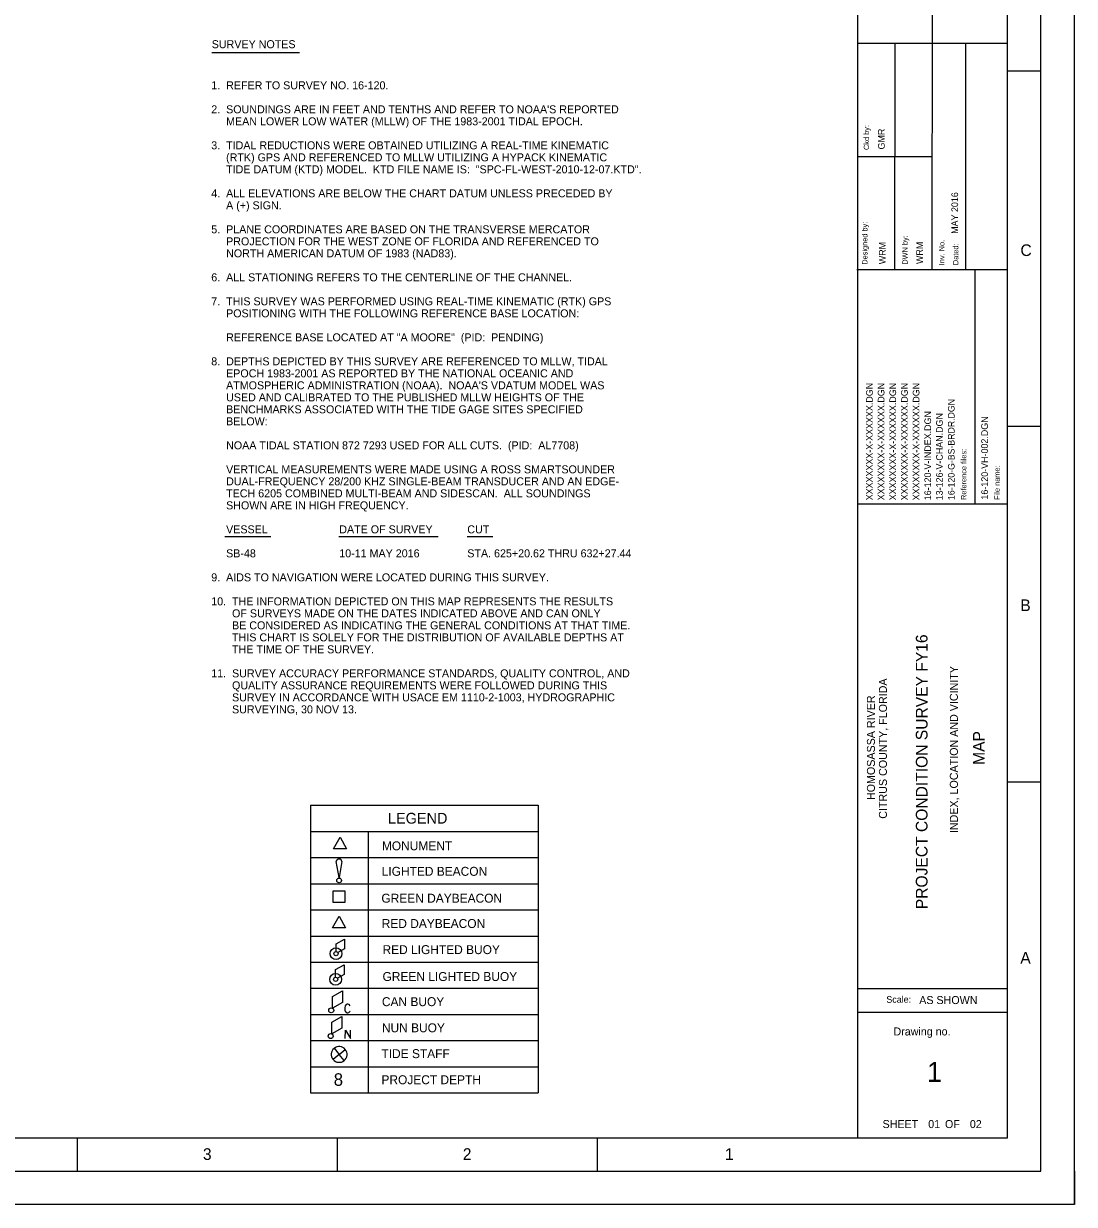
# Model space of a CAD drawing. Extents: x 384865 to 516869, y 1553900 to 1655899.
# Drawn here: x 469592 to 516869, y 1553900 to 1607032 of the extents above; entities that cross this region are included whole.
import ezdxf

# ---------------------------------------------------------------- set-up
doc = ezdxf.new("R2010")
doc.units = 0
for name, color, linetype in [('G-ANNO-NPLT', 7, 'Continuous'), ('G-ANNO-TEXT-DRWG', 7, 'Continuous'), ('G-ANNO-TEXT-PROJ', 7, 'Continuous'), ('G-ANNO-TEXT-TTLB', 7, 'Continuous'), ('G-ANNO-TTLB', 7, 'Continuous'), ('V-ANNO-LEGN', 7, 'Continuous'), ('V-ANNO-TEXT', 7, 'Continuous')]:
    doc.layers.add(name, color=color, linetype=linetype)

msp = doc.modelspace()

# ---------------------------------------------------------------- linework, layer by layer
at = {"layer": 'G-ANNO-NPLT'}
msp.add_lwpolyline([(384865, 1655899), (516865, 1655899), (516865, 1553900), (384865, 1553900)], close=True, dxfattribs=at)
msp.add_lwpolyline([(516869, 1555400), (516869, 1553900), (515369, 1553900)], dxfattribs=at)
at = {"layer": 'G-ANNO-TTLB'}
for p, q in [((507114, 1652899), (507114, 1556900)), ((510470, 1595964), (510490, 1621751)), ((507091, 1606154), (513865, 1606154)), ((508791, 1595966), (508799, 1606154)), ((511976, 1606154), (511976, 1595964)), ((515365, 1604896), (513865, 1604896)), ((507091, 1601059), (510474, 1601059)), ((507078, 1595964), (513865, 1595964)), ((512386, 1595964), (512386, 1585423)), ((515365, 1588897), (513865, 1588897)), ((507114, 1585423), (513865, 1585423)), ((515365, 1572899), (513865, 1572899)), ((507114, 1563613), (513865, 1563613)), ((507114, 1562542), (513865, 1562542)), ((472015, 1555400), (472015, 1556900)), ((483715, 1555400), (483715, 1556900)), ((495415, 1555400), (495415, 1556900))]:
    msp.add_line(p, q, dxfattribs=at)
for points in [[(386365, 1555400), (515365, 1555400), (515365, 1654399), (386365, 1654399)], [(513865, 1652899), (390115, 1652899), (390115, 1556900), (513865, 1556900)]]:
    msp.add_lwpolyline(points, close=True, dxfattribs=at)
at = {"layer": 'V-ANNO-LEGN'}
for p, q in [((482493, 1571859), (482493, 1558917)), ((482493, 1571859), (492742, 1571859)), ((492742, 1571859), (492742, 1558917)), ((482493, 1570682), (492742, 1570682)), ((485088, 1570677), (485088, 1558917)), ((483529, 1569904), (483828, 1570419)), ((483828, 1570419), (484122, 1569905)), ((484124, 1569902), (483529, 1569904)), ((482493, 1569506), (492742, 1569506)), ((483787, 1568614), (483662, 1569325)), ((483913, 1569325), (483787, 1568614)), ((482493, 1568330), (492742, 1568330)), ((482493, 1567153), (492742, 1567153)), ((483484, 1566350), (483784, 1566864)), ((483784, 1566864), (484078, 1566350)), ((484080, 1566347), (483484, 1566350)), ((482493, 1565976), (492742, 1565976)), ((483648, 1565622), (484028, 1565841)), ((484028, 1565841), (484028, 1565403)), ((483649, 1565277), (483648, 1565622)), ((484028, 1565403), (483730, 1565230)), ((482493, 1564800), (492742, 1564800)), ((483630, 1564465), (484010, 1564684)), ((483630, 1564120), (483630, 1564465)), ((484010, 1564246), (483712, 1564073)), ((484010, 1564684), (484010, 1564246)), ((482493, 1563623), (492742, 1563623)), ((483485, 1563249), (483936, 1563511)), ((483485, 1562728), (483485, 1563249)), ((483936, 1563511), (483937, 1562989)), ((483937, 1562989), (483485, 1562728)), ((482493, 1562447), (492742, 1562447)), ((483461, 1561571), (483463, 1562092)), ((483463, 1562092), (483916, 1562351)), ((483916, 1562351), (483914, 1561830)), ((483914, 1561830), (483461, 1561571)), ((482493, 1561270), (492742, 1561270)), ((483790, 1560647), (483516, 1560420)), ((483562, 1560922), (483790, 1560647)), ((483790, 1560647), (484064, 1560875)), ((484018, 1560373), (483790, 1560647)), ((482493, 1560093), (492742, 1560093)), ((482493, 1558917), (492742, 1558917))]:
    msp.add_line(p, q, dxfattribs=at)
msp.add_lwpolyline([(483521, 1567478), (483521, 1568009), (484052, 1568009), (484052, 1567477)], close=True, dxfattribs=at)
for points in [[(484283, 1562832), (484235, 1562895), (484187, 1562906), (484154, 1562906), (484109, 1562894), (484058, 1562831), (484046, 1562748), (484047, 1562703), (484047, 1562673), (484050, 1562646), (484059, 1562598), (484110, 1562538), (484155, 1562526), (484182, 1562526), (484232, 1562538), (484283, 1562598)], [(484066, 1561363), (484068, 1561743), (484303, 1561362), (484304, 1561742)]]:
    msp.add_lwpolyline(points, dxfattribs=at)
for centre, radius in [((483786, 1568478), 107), ((483648, 1565183), 266), ((483648, 1565183), 93.7), ((483630, 1564026), 266), ((483630, 1564026), 93.7), ((483432, 1562630), 112), ((483407, 1561473), 112)]:
    msp.add_circle(centre, radius, dxfattribs=at)
for centre, radius, start, end in [((483787, 1569315), 126, 4.6442, 175.3545), ((483790, 1560647), 356, 129.6858, 219.6858), ((483790, 1560647), 356, 39.6856, 129.6858), ((483790, 1560647), 356, 309.6858, 39.6859), ((483790, 1560647), 356, 219.6858, 309.6858)]:
    msp.add_arc(centre, radius, start, end, dxfattribs=at)
at = {"layer": 'V-ANNO-TEXT'}
for p, q in [((478057, 1605734), (482005, 1605734)), ((478648, 1583959), (480714, 1583959)), ((483772, 1583959), (488244, 1583959)), ((489542, 1583959), (490700, 1583959))]:
    msp.add_line(p, q, dxfattribs=at)

# ---------------------------------------------------------------- texts
at = {"layer": 'G-ANNO-TEXT-DRWG'}
for s, height, p in [('GMR', 300, (508336, 1601369)), ('WRM', 300, (508382, 1596207)), ('WRM', 300, (510051, 1596214)), ('XXXXXXXX-X-XXXXXX.DGN', 300, (507797, 1585583)), ('XXXXXXXX-X-XXXXXX.DGN', 300, (508322, 1585583)), ('XXXXXXXX-X-XXXXXX.DGN', 300, (508847, 1585583)), ('XXXXXXXX-X-XXXXXX.DGN', 300, (509372, 1585583)), ('XXXXXXXX-X-XXXXXX.DGN', 300, (509897, 1585583)), ('16-120-V-INDEX.DGN', 300, (510422, 1585583)), ('13-126-V-CHAN.DGN', 300, (510947, 1585583)), ('16-120-VH-002.DGN', 300, (512978, 1585614)), ('INDEX, LOCATION AND VICINITY', 360, (511627, 1570607)), ('MAP', 524.9, (512832, 1573676))]:
    msp.add_text(s, height=height, rotation=90, dxfattribs=at).set_placement(p)
for s, height, p in [('1', 900, (510239, 1559414)), (' 01          02', 360, (510159, 1557334))]:
    msp.add_text(s, height=height, dxfattribs=at).set_placement(p)
at = {"layer": 'G-ANNO-TEXT-PROJ'}
for s, height, p in [('MAY 2016', 300, (511637, 1597572)), ('16-120-G-BS-BRDR.DGN', 294, (511477, 1585595)), ('PROJECT CONDITION SURVEY FY16', 525, (510261, 1567182)), ('CITRUS COUNTY, FLORIDA', 360, (508435, 1571253)), ('HOMOSASSA RIVER', 360, (507895, 1572095))]:
    msp.add_text(s, height=height, rotation=90, dxfattribs=at).set_placement(p)
at = {"layer": 'G-ANNO-TEXT-TTLB'}
for s, p in [('Ckd by:', (507632, 1601344)), ('Designed by:', (507559, 1596182)), ('DWN by:', (509365, 1596183)), ('Inv. No.', (511022, 1596161)), ('Dated:', (511647, 1596164)), ('Reference files:', (512008, 1585597)), ('File name:', (513507, 1585604))]:
    msp.add_text(s, height=240, rotation=90, dxfattribs=at).set_placement(p)
for s, height, p in [('Scale:', 300, (508408, 1562971)), ('AS SHOWN', 360, (509888, 1562914)), ('Drawing no.', 360, (508729, 1561501)), ('SHEET         OF', 360, (508238, 1557334))]:
    msp.add_text(s, height=height, dxfattribs=at).set_placement(p)
at = {"layer": 'G-ANNO-TTLB'}
for s, p in [('C', (514442, 1596574)), ('B', (514436, 1580598)), ('A', (514436, 1564735)), ('3', (477660, 1555900)), ('2', (489353, 1555900)), ('1', (501147, 1555900))]:
    msp.add_text(s, height=525, dxfattribs=at).set_placement(p)
at = {"layer": 'V-ANNO-LEGN'}
for s, height, p in [('LEGEND', 486.7, (485985, 1571032)), ('MONUMENT', 401.5, (485713, 1569833)), ('LIGHTED BEACON', 401.54, (485705, 1568686)), ('GREEN DAYBEACON', 401.54, (485690, 1567476)), ('RED DAYBEACON', 401.54, (485705, 1566337)), ('RED LIGHTED BUOY', 401.54, (485741, 1565162)), ('GREEN LIGHTED BUOY', 401.54, (485741, 1563952)), ('CAN BUOY', 401.5, (485713, 1562821)), ('NUN BUOY', 401.5, (485713, 1561644)), ('TIDE STAFF', 401.5, (485693, 1560482)), ('8', 563, (483546, 1559237)), ('PROJECT DEPTH', 401.54, (485693, 1559308))]:
    msp.add_text(s, height=height, rotation=360, dxfattribs=at).set_placement(p)
at = {"layer": 'V-ANNO-TEXT'}
for s, p in [('SURVEY NOTES', (478056, 1605925)), ('1.  REFER TO SURVEY NO. 16-120.', (478034, 1604075)), ("2.  SOUNDINGS ARE IN FEET AND TENTHS AND REFER TO NOAA'S REPORTED", (478034, 1602995)), ('     MEAN LOWER LOW WATER (MLLW) OF THE 1983-2001 TIDAL EPOCH.', (478034, 1602455)), ('3.  TIDAL REDUCTIONS WERE OBTAINED UTILIZING A REAL-TIME KINEMATIC', (478034, 1601375)), ('     (RTK) GPS AND REFERENCED TO MLLW UTILIZING A HYPACK KINEMATIC', (478034, 1600835)), ('     TIDE DATUM (KTD) MODEL.  KTD FILE NAME IS:  "SPC-FL-WEST-2010-12-07.KTD".', (478034, 1600295)), ('4.  ALL ELEVATIONS ARE BELOW THE CHART DATUM UNLESS PRECEDED BY', (478034, 1599215)), ('     A (+) SIGN.', (478034, 1598675)), ('5.  PLANE COORDINATES ARE BASED ON THE TRANSVERSE MERCATOR', (478034, 1597595)), ('     PROJECTION FOR THE WEST ZONE OF FLORIDA AND REFERENCED TO', (478034, 1597055)), ('     NORTH AMERICAN DATUM OF 1983 (NAD83).', (478034, 1596515)), ('6.  ALL STATIONING REFERS TO THE CENTERLINE OF THE CHANNEL.', (478034, 1595435)), ('7.  THIS SURVEY WAS PERFORMED USING REAL-TIME KINEMATIC (RTK) GPS', (478034, 1594355)), ('     POSITIONING WITH THE FOLLOWING REFERENCE BASE LOCATION:', (478034, 1593815)), ('     REFERENCE BASE LOCATED AT "A MOORE"  (PID:  PENDING)', (478034, 1592735)), ('8.  DEPTHS DEPICTED BY THIS SURVEY ARE REFERENCED TO MLLW, TIDAL', (478034, 1591655)), ('     EPOCH 1983-2001 AS REPORTED BY THE NATIONAL OCEANIC AND', (478034, 1591115)), ("     ATMOSPHERIC ADMINISTRATION (NOAA).  NOAA'S VDATUM MODEL WAS", (478034, 1590575)), ('     USED AND CALIBRATED TO THE PUBLISHED MLLW HEIGHTS OF THE ', (478034, 1590035)), ('     BENCHMARKS ASSOCIATED WITH THE TIDE GAGE SITES SPECIFIED', (478034, 1589495)), ('     BELOW:', (478034, 1588955)), ('     NOAA TIDAL STATION 872 7293 USED FOR ALL CUTS.  (PID:  AL7708)', (478034, 1587875)), ('     VERTICAL MEASUREMENTS WERE MADE USING A ROSS SMARTSOUNDER', (478034, 1586795)), ('     DUAL-FREQUENCY 28/200 KHZ SINGLE-BEAM TRANSDUCER AND AN EDGE-', (478034, 1586255)), ('     TECH 6205 COMBINED MULTI-BEAM AND SIDESCAN.  ALL SOUNDINGS', (478034, 1585715)), ('     SHOWN ARE IN HIGH FREQUENCY.', (478034, 1585175)), ('     VESSEL', (478034, 1584095)), ('DATE OF SURVEY', (483794, 1584095)), ('CUT', (489554, 1584095)), ('     SB-48', (478034, 1583015)), ('10-11 MAY 2016', (483794, 1583015)), ('STA. 625+20.62 THRU 632+27.44', (489554, 1583015)), ('9.  AIDS TO NAVIGATION WERE LOCATED DURING THIS SURVEY.', (478034, 1581935)), ('10.  THE INFORMATION DEPICTED ON THIS MAP REPRESENTS THE RESULTS', (478034, 1580855)), ('       OF SURVEYS MADE ON THE DATES INDICATED ABOVE AND CAN ONLY', (478034, 1580315)), ('       BE CONSIDERED AS INDICATING THE GENERAL CONDITIONS AT THAT TIME.', (478034, 1579775)), ('       THIS CHART IS SOLELY FOR THE DISTRIBUTION OF AVAILABLE DEPTHS AT', (478034, 1579235)), ('       THE TIME OF THE SURVEY.', (478034, 1578695)), ('11.  SURVEY ACCURACY PERFORMANCE STANDARDS, QUALITY CONTROL, AND', (478034, 1577615)), ('       QUALITY ASSURANCE REQUIREMENTS WERE FOLLOWED DURING THIS', (478034, 1577075)), ('       SURVEY IN ACCORDANCE WITH USACE EM 1110-2-1003, HYDROGRAPHIC', (478034, 1576535)), ('       SURVEYING, 30 NOV 13.    ', (478034, 1575995))]:
    msp.add_text(s, height=360, dxfattribs=at).set_placement(p)

doc.saveas('drawing.dxf')
